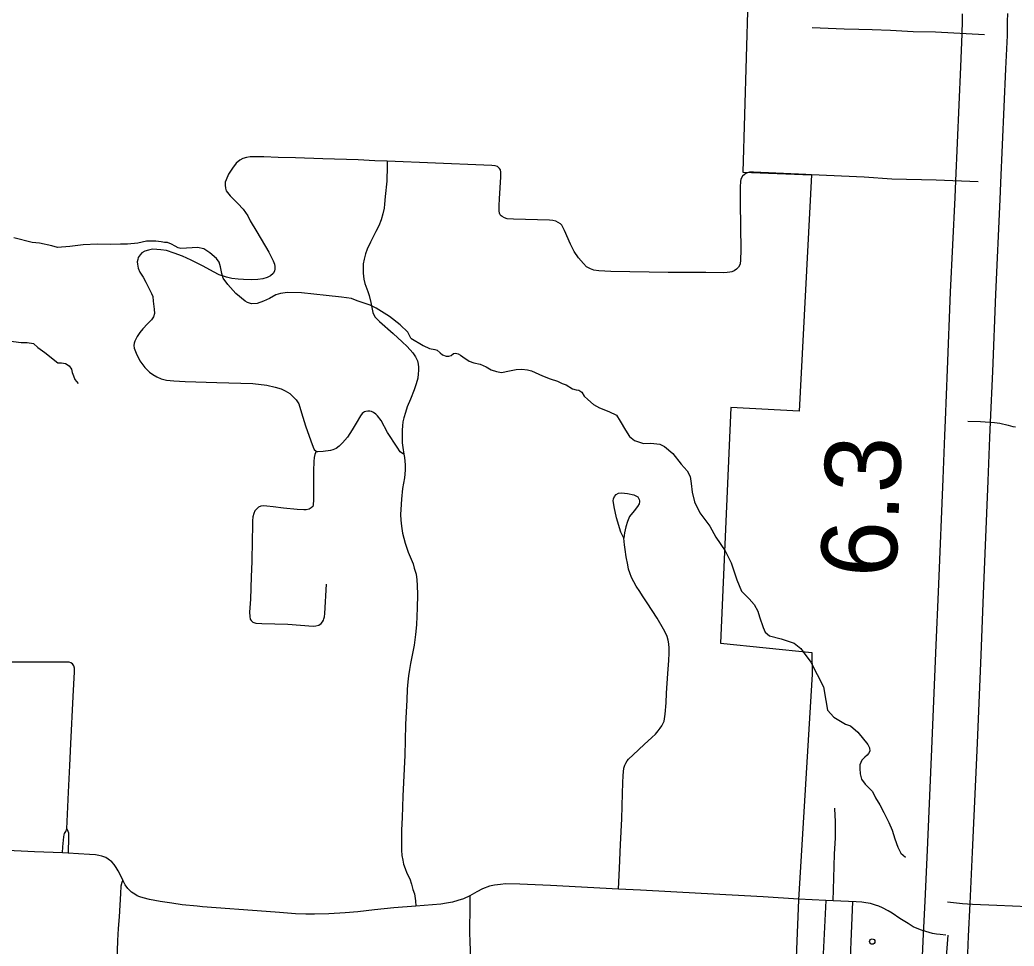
# Model space of a CAD drawing. Extents: x 653372 to 905732, y 627442 to 787275.
# Drawn here: x 684356 to 689902, y 750128 to 755293 of the extents above; entities that cross this region are included whole.
import ezdxf

# ---------------------------------------------------------------- set-up
doc = ezdxf.new("R2010")
doc.units = 0
for name, color, linetype in [('15', 7, 'Continuous'), ('33', 7, 'Continuous'), ('34', 7, 'Continuous'), ('35', 7, 'Continuous'), ('48', 7, 'Continuous'), ('57', 7, 'Continuous'), ('6', 7, 'Continuous')]:
    doc.layers.add(name, color=color, linetype=linetype)

msp = doc.modelspace()

# ---------------------------------------------------------------- linework, layer by layer
at = {"layer": '15'}
for points in [[(689519.6, 753060.5), (689531.2, 753342.1), (689548.2, 753773.6), (689572.7, 754302.1), (689576.4, 754395.3), (689605, 755029.9), (689612.9, 755214.1), (689614.3, 755287), (689614.8, 755325.5)], [(689864.8, 755329), (689864.3, 755283.1), (689862.8, 755206.4), (689854.8, 755018.9), (689826.2, 754384.7), (689822.5, 754291.3), (689798, 753762.9), (689781, 753332), (689769.4, 753050.2)], [(689386.5, 749952.9), (689396.2, 750194.9), (689405.6, 750377.4), (689419, 750662.4), (689445.9, 751269.7), (689466.3, 751762.7), (689482.6, 752146.3), (689505.8, 752732.5), (689516.2, 752975), (689519.6, 753060.5)], [(689769.4, 753050.2), (689766, 752964.7), (689755.6, 752722.2), (689732.4, 752136.1), (689716.1, 751752.2), (689695.7, 751258.9), (689668.7, 750651), (689655.3, 750365.1), (689645.9, 750183.4), (689636.3, 749941.9)]]:
    msp.add_lwpolyline(points, dxfattribs=at)
at = {"layer": '33'}
for points in [[(688775.2, 755250), (688953.6, 755241.8), (689035.3, 755240.7), (689111.4, 755238.5), (689212.8, 755236.1), (689338.5, 755227.4), (689464.3, 755225.7), (689737.9, 755210.3)], [(686405.1, 754504.9), (686335.6, 754506.8), (686242.8, 754512.2), (686045.9, 754517.6), (685893.7, 754522.7), (685797.7, 754525.6), (685717.1, 754529), (685640.4, 754529.2), (685620.3, 754525.6), (685599.7, 754520.5), (685583.1, 754511), (685562.7, 754493.2), (685541.4, 754466), (685519.9, 754433), (685506.9, 754401.4), (685502.2, 754386.8), (685501.2, 754370.5), (685503.4, 754354.7), (685507.1, 754339.4), (685528.3, 754311.8), (685540.6, 754299.8), (685572.3, 754268.9), (685601.7, 754236.5), (685626.9, 754200.6), (685640.7, 754171.2), (685677.8, 754111.3)], [(686405.1, 754504.9), (686405.9, 754476.6), (686402.3, 754392.7), (686393.9, 754308.4), (686390.5, 754265.7), (686387.7, 754243.3), (686381.3, 754210.3), (686372.3, 754177.4), (686358.5, 754143.5), (686342, 754112.3), (686311.9, 754052.7), (686293.6, 754013.2), (686284.2, 753987.7), (686276.4, 753959.1), (686271.9, 753932.5), (686270.5, 753905.2), (686270.3, 753881.1), (686272.5, 753863.9), (686275.2, 753846.7), (686280.9, 753821.9), (686297.7, 753777.4), (686304.6, 753755.8), (686313.6, 753717), (686325.3, 753661.5), (686336.8, 753636), (686361.7, 753610.1), (686438.3, 753543.1), (686489.4, 753496.6), (686516.9, 753471), (686548.5, 753435.2), (686563.3, 753412.9), (686573.4, 753390.6), (686577.1, 753372.8), (686579.8, 753356.2), (686579.8, 753337.4), (686578.7, 753318.7), (686575.9, 753295.3), (686566.9, 753262.4), (686555.2, 753230.1), (686535.4, 753178.2), (686516.5, 753134.2), (686507, 753102.9), (686497.5, 753072.7), (686492.6, 753051.4), (686490.3, 753029), (686488.5, 753005), (686488, 752971.8), (686489, 752933.8), (686492.5, 752907.5), (686497.9, 752871.5)], [(689701.3, 754390), (689466.7, 754397.9), (689219.8, 754405.3), (689065.8, 754415.4), (688771.7, 754428.8), (688741.3, 754430.2), (688449.2, 754442.9), (688427.1, 754442.9), (688409, 754438.6), (688397.7, 754430.7), (688387.1, 754420.6), (688377.6, 754403.7), (688376.5, 754391.3), (688374.3, 754361.6), (688373.8, 754346.4), (688373.7, 754273.2), (688377.5, 754007.7), (688376.5, 753953.9), (688373.8, 753930.5), (688364.9, 753912.8), (688353.6, 753902.1), (688340.9, 753892.8), (688326.9, 753887.7), (688317.2, 753885.9), (688302.6, 753883.6), (688281.2, 753882.8), (688183.2, 753883), (687972.9, 753883.8), (687652.4, 753889.3), (687584.9, 753894.1), (687558.8, 753897.6), (687539.7, 753904.4), (687517.9, 753916.1), (687500.5, 753934.6), (687473.2, 753965.8), (687448, 754001.8), (687427.8, 754041.8), (687394.9, 754118.7), (687379.9, 754147.5), (687371.2, 754156), (687359, 754163.3), (687346.1, 754170.6), (687330, 754174.5), (687310.1, 754176.5), (687109.3, 754181.9), (687074.8, 754183.6), (687059.1, 754188.2), (687046.2, 754196.2), (687040.8, 754200.5), (687036.1, 754204.8), (687030.9, 754213.9), (687029.2, 754228.5), (687029.4, 754257.5), (687031.2, 754294.7), (687039.1, 754417.8), (687039.2, 754444.1), (687036.8, 754457.2), (687031.5, 754463.6), (687020.1, 754474.3), (687007.7, 754478.1), (686989.2, 754480.8), (686944.3, 754482.1), (686405.1, 754504.9)], [(685100.4, 753723.5), (685105.4, 753678.6), (685106.3, 753655), (685101.5, 753637.3), (685090, 753619.2), (685067.8, 753597.3), (685042.3, 753569.7), (685025.4, 753549.2), (685010.5, 753527.4), (684998.2, 753501), (684994.2, 753489.6), (684992.7, 753477.5), (684994.4, 753462.8), (685004.1, 753434.6), (685025.3, 753390.9), (685052.6, 753354.4), (685079.6, 753327.8), (685098.1, 753314.6), (685120.8, 753301.4), (685143.6, 753291.2), (685174.9, 753284), (685214.2, 753280.2), (685278.7, 753276.1), (685454.8, 753270.1), (685655, 753264.3), (685734, 753255.6), (685780.9, 753244.2), (685814.3, 753234.3), (685836, 753224.2), (685861.8, 753208.7), (685879.2, 753192.9), (685896.5, 753174.6), (685911.6, 753152.3), (685927.9, 753101.4), (685948.9, 753029.3), (685978.9, 752945.9), (685991.7, 752909.4), (685998.6, 752896.7), (686009.4, 752886.8), (686016.6, 752884)], [(686497.9, 752871.5), (686490.2, 752874), (686478.2, 752884), (686460.3, 752910.7), (686407, 752991.6), (686371.6, 753058.4), (686351, 753085.3), (686342.2, 753094.6), (686328, 753103.1), (686318, 753108.7), (686309, 753111.2), (686297.2, 753111.5), (686286.5, 753109.7), (686279.4, 753106.7), (686273.5, 753103.7), (686265.8, 753096.9), (686256.3, 753084.9), (686231.5, 753042.8), (686209.8, 753007.1), (686183.5, 752966.2), (686155.7, 752933.8), (686136.5, 752915.1), (686120.1, 752903.3), (686101.6, 752895.8), (686089.8, 752891.9), (686048.9, 752885.6), (686016.6, 752884)], [(689644.5, 753055.3), (689714.7, 753053.7), (689793.6, 753048), (689823.6, 753043.2), (689868.8, 753032.5), (689894.9, 753025.4), (689910.1, 753022.8)], [(686497.9, 752871.5), (686502.6, 752851.4), (686505.4, 752811.1), (686505.8, 752780.9), (686502.6, 752738.8), (686490, 752678.8), (686484.2, 752619.3), (686481.2, 752563), (686479, 752534.2), (686482.1, 752502.6), (686484.4, 752469), (686489.9, 752429.6), (686505.7, 752374.8), (686522.3, 752324.6), (686549.9, 752260.1), (686556.5, 752235.7), (686566.9, 752202.3), (686571.3, 752170.6), (686573, 752137.7), (686573.5, 752087.4), (686572.6, 752011.7), (686571.2, 751966.8), (686567.8, 751919.9), (686562.2, 751865.5), (686555, 751805.3), (686544, 751750.7), (686535.2, 751704), (686530.1, 751669.9), (686523.7, 751633.9), (686520.7, 751601.1), (686516.1, 751560.8), (686514.9, 751498.4), (686511, 751433.5), (686508.2, 751363.2), (686505.5, 751274), (686503.8, 751192.9), (686492.8, 750963.2), (686487.9, 750845.3), (686485.8, 750774.9), (686484.7, 750714.6), (686485.8, 750662.9), (686487.6, 750632.3), (686491.5, 750607.3), (686496.9, 750584.4), (686505.5, 750559.5), (686515.5, 750533.5), (686531.3, 750502.2), (686540.5, 750473.1), (686549, 750444), (686556.9, 750418.2), (686563.1, 750380), (686565.6, 750351.1)], [(687726, 752403), (687708.3, 752436.7), (687685, 752516.3), (687671.9, 752576.6), (687666.7, 752600.5), (687665, 752610.8), (687667.3, 752621), (687673.6, 752634.2), (687683.4, 752645.3), (687695, 752652.5), (687711.3, 752655.2), (687746.3, 752652.1), (687781.2, 752644), (687792.5, 752639.3), (687802.9, 752633.1), (687807.8, 752625.4), (687811.2, 752618.6), (687812.6, 752611.5), (687812.7, 752604.8), (687810, 752593.4), (687802.1, 752579), (687782, 752555.2), (687756.6, 752522.4), (687745.2, 752495.9), (687736, 752465.4), (687729.8, 752432.1), (687726, 752403)], [(687694.8, 750445.3), (687701.1, 750562.7), (687707.4, 750693.5), (687713.7, 750837), (687717.9, 750978.1), (687719.3, 751037.9), (687721.3, 751079.6), (687723.1, 751098.9), (687726.1, 751119.9), (687730.9, 751136.3), (687735.6, 751146.8), (687743.9, 751161.1), (687750.5, 751169.6), (687778, 751194.4), (687839.3, 751251.4), (687880.7, 751290), (687901.4, 751309.9), (687916.9, 751327.6), (687928.4, 751342.2), (687937.3, 751356.7), (687944.9, 751370.3), (687949.9, 751382.3), (687952.7, 751395.7), (687955, 751420.4), (687960.9, 751484.6), (687964.1, 751538.1), (687971.3, 751646.9), (687977, 751719.8), (687978.3, 751760.4), (687978.4, 751789.9), (687977.1, 751813.3), (687973.4, 751833.5), (687967.3, 751854.3), (687958.4, 751875.1), (687946.4, 751895.2), (687910.8, 751955.8), (687856.2, 752041.9), (687829.9, 752080.6), (687814.8, 752104.3), (687794.1, 752134.5), (687780.2, 752159.8), (687768.7, 752183.4), (687758.4, 752209), (687752, 752230.1), (687746.8, 752254.3), (687739, 752298.7), (687732, 752339.7), (687729.2, 752365.8), (687726, 752403)], [(684618.7, 750781.5), (684627.2, 750986.4), (684635.2, 751135.5), (684640.5, 751255.2), (684652.5, 751519), (684660.2, 751657.4), (684660.8, 751677.8), (684656.5, 751689.7), (684649.2, 751701), (684641.2, 751707.7), (684631.4, 751711.5), (684621.5, 751711.8), (684311.4, 751710.6), (683991.3, 751710.8), (683355.8, 751710)], [(684594.2, 750647.4), (684596.1, 750681.2), (684601, 750737.8), (684603, 750747.7), (684605.9, 750755), (684611.8, 750766.8), (684618.7, 750781.5), (684624.1, 750767.6), (684627.1, 750758.4), (684628.2, 750749), (684628.2, 750737.6), (684625.1, 750645.6)], [(685262.3, 750358.6), (685204.3, 750366.1), (685137.9, 750377.1), (685078.6, 750388), (685044.1, 750396.7), (685024.7, 750403), (685011.1, 750408.6), (684996.5, 750417.6), (684979.7, 750429.1), (684958.9, 750448.8), (684943.7, 750468.4), (684929.7, 750495), (684917.7, 750522.6), (684904.6, 750547.3), (684893.7, 750565.7), (684882.3, 750583.2), (684869.1, 750597.9), (684849.5, 750612.3), (684835.9, 750620.8), (684812.4, 750629.6), (684796.3, 750633.5), (684778.7, 750636.4), (684744.9, 750638.4), (684683.5, 750642.6), (684625.1, 750645.6), (684594.2, 750647.4), (684438, 750653.3), (684250.7, 750661.7)], [(689521, 750189.2), (689489.5, 750192.4), (689468.8, 750194.4), (689448, 750198.3), (689410.8, 750209.5), (689380.1, 750218.5), (689339.7, 750235.9), (689310.6, 750252.9), (689265.8, 750281.8), (689221.7, 750311.3), (689200.6, 750324.7), (689168.8, 750340.5), (689148.3, 750349.8), (689128.3, 750356.5), (689101, 750364.7), (689075.6, 750369.5), (689052.2, 750373.5), (689021.4, 750375.1), (688892.9, 750380.5), (688851.9, 750381.6), (688699.6, 750388.8), (688503.4, 750402.1), (688157.1, 750421.3), (687819, 750438.8), (687694.8, 750445.3), (687316.4, 750466), (687145.7, 750473.1), (687065.8, 750474.2), (687036.8, 750471), (687004.4, 750467.3), (686976.1, 750462.1), (686936.6, 750447.1), (686905.2, 750429.9), (686866.8, 750407.6), (686830.2, 750391.9), (686799.3, 750381.8), (686769.1, 750372.9), (686736.4, 750367.1), (686704.7, 750362), (686657.5, 750357.4), (686565.6, 750351.1), (686441.6, 750341), (686335.1, 750329.5), (686242, 750318.8), (686170.3, 750312.9), (686080.1, 750308.2), (685998.8, 750306.6), (685950.4, 750306.1), (685893.4, 750308.4), (685804.9, 750314.5), (685729.8, 750320.8), (685375, 750346.2), (685345.5, 750349.8), (685262.3, 750358.6)], [(686866.8, 750407.6), (686865.9, 750378), (686865.3, 750318.3), (686863.5, 750241.3), (686865.1, 750198.3), (686865.7, 750157.7), (686870.4, 750044.5)], [(688851.9, 750381.6), (688827.3, 749899.1), (688811.5, 749450.7), (688797.9, 749228.5), (688799.3, 749199.4), (688808, 749180.6), (688822.6, 749165.1), (688843.3, 749157.5), (688860.6, 749155.8), (689243.8, 749139.1)], [(689530.6, 750373.9), (689564.9, 750370.1), (689615.2, 750365.8), (689669.7, 750362.1), (689805.2, 750355.2), (690068, 750345.2)]]:
    msp.add_lwpolyline(points, dxfattribs=at)
at = {"layer": '34'}
for points in [[(685677.8, 754111.3), (685744.8, 753996.4), (685769.1, 753948.9), (685776.9, 753930.3), (685778.1, 753918.2), (685778.2, 753904), (685775.7, 753890.9), (685769.1, 753879), (685753.4, 753864.8), (685735.8, 753855.9), (685712, 753849.2), (685683.5, 753844.3), (685648.2, 753842.2), (685604.2, 753845.1), (685573.3, 753846.6), (685538.2, 753850.8), (685509, 753858.5), (685466.9, 753871.3), (685435.4, 753888.5), (685378.9, 753919.1), (685311.6, 753952.7), (685264, 753974.6), (685216.7, 753992.3), (685173.5, 754005.7), (685142.7, 754010.8), (685120.2, 754013.1), (685095.5, 754013.8), (685073.3, 754009.2), (685052.7, 754003.5), (685035.5, 753993), (685026.3, 753982.8), (685016.4, 753967.8), (685013.4, 753956.9), (685010.4, 753943.9), (685012.6, 753929.6), (685016.7, 753908.5), (685025, 753886.7), (685043.6, 753858.3), (685058.5, 753829.5), (685075.3, 753796.7), (685089.6, 753766.3), (685097, 753749.8), (685100.4, 753723.5)], [(686009.4, 752886.8), (686001.5, 752868.2), (685997.8, 752852.6), (685995.1, 752830.1), (685993.5, 752778.1), (685993.4, 752616.8), (685992, 752588.5), (685989.7, 752579.7), (685981.7, 752570.7), (685970.8, 752564.5), (685953.9, 752560.8), (685940.2, 752560.1), (685903.5, 752561.7), (685826.5, 752569.3), (685769.2, 752576.6), (685733.6, 752580.2), (685715.7, 752582.1), (685700.5, 752580.5), (685687.7, 752575.1), (685675.3, 752564.9), (685667.7, 752555.2), (685660.9, 752540.1), (685656.2, 752521.4), (685654.4, 752499.4), (685654, 752468.7), (685652.2, 752390.5), (685649.7, 752271.8), (685645.6, 752187.7), (685641.8, 752062.3), (685636.5, 751989.4), (685638.4, 751964.7), (685640.1, 751951), (685646.1, 751942.9), (685656.4, 751934.7), (685662.1, 751931.4), (685673, 751928.4), (685705, 751927.5), (685850.3, 751922.1), (685992.9, 751912), (686007.1, 751913.1), (686024, 751917.9), (686036.4, 751927), (686043.5, 751935.2), (686049, 751944.5), (686052.4, 751951.7), (686054.8, 751964.2), (686057, 751983.1), (686066.4, 752146.2)], [(688892.9, 750380.5), (688897.2, 750506.1), (688900.1, 750640), (688905.7, 750730.7), (688905.8, 750773), (688905.6, 750825.7), (688904.2, 750854.8), (688901.4, 750897.7)], [(684929.7, 750495), (684924.4, 750481.5), (684919.9, 750461.9), (684916.9, 750421.8), (684909.1, 750291.2), (684904, 750225.7), (684901.6, 750158.2), (684897.7, 750042.8)]]:
    msp.add_lwpolyline(points, dxfattribs=at)
at = {"layer": '35'}
for points in [[(686536.8, 753518.3), (686521, 753551.4), (686478.3, 753592.6), (686417.2, 753638.4), (686342.8, 753684.5), (686310, 753701.5), (686237.6, 753726.3), (686206.4, 753738.5), (686150.7, 753745.5), (686065.3, 753756.1), (685926.7, 753770.2), (685849.2, 753772.5), (685809.7, 753766.4), (685783.6, 753758.5), (685747.7, 753739.6), (685715.3, 753723.3), (685679.7, 753710.4), (685647.7, 753709.4), (685626.7, 753716.7), (685612.7, 753723.7), (685560.8, 753766.6), (685515.7, 753817.1), (685490.8, 753851.8), (685483.6, 753878), (685476.1, 753915.4), (685468.2, 753941.6), (685452.2, 753962.1), (685415.3, 753994.3), (685382, 754015.3), (685346.3, 754023), (685316.4, 754021.9), (685285.7, 754019.5), (685254.4, 754018.5), (685239.9, 754021.6), (685222.9, 754030.7), (685201.3, 754042), (685178.9, 754051.3), (685162.5, 754051.7), (685143.6, 754055.2), (685114.9, 754058.5), (685063.2, 754058.8), (685013.6, 754048.3), (684956.2, 754041.4), (684917, 754041.2), (684864.4, 754040.1), (684788.7, 754041.7), (684709.4, 754037.5), (684634.7, 754028.4), (684565.7, 754024.1), (684533.7, 754032.7), (684465.2, 754047.5), (684425.4, 754050.7), (684322.2, 754077.7)], [(683875.5, 753777.5), (683928.3, 753714.2), (683992, 753674.7), (684058.7, 753654.9), (684087.2, 753637.3), (684124.4, 753616.3), (684162.4, 753592), (684197.3, 753560), (684225.2, 753524.3), (684277.9, 753504.7), (684363.3, 753494.1), (684397.1, 753493.1), (684432.8, 753488.1), (684456.1, 753465.4), (684495.1, 753438.3), (684567.1, 753380.4), (684588.7, 753380), (684609.8, 753376.9), (684631.2, 753364), (684643.3, 753345.2), (684647.7, 753326.1), (684655.1, 753306.9), (684663.5, 753287.8), (684681.7, 753264.3)], [(686536.8, 753518.3), (686606.7, 753477.6), (686641.3, 753459.3), (686670.2, 753454.9), (686684.6, 753450.4), (686700.7, 753436.8), (686714.2, 753424.6), (686734.7, 753417.8), (686749.1, 753416.6), (686761.7, 753421.8), (686775.2, 753433.1), (686787, 753434.9), (686800.6, 753430.3), (686813.5, 753423), (686827.7, 753412.9), (686862.7, 753389.1), (686888.6, 753379.3), (686923, 753372.8), (686957, 753357.9), (686985.5, 753340.5), (687014.3, 753332), (687043.1, 753325.6), (687086.8, 753334.7), (687124.3, 753342.5), (687156.2, 753344.3), (687188.5, 753341.3), (687210.4, 753335.1), (687272, 753307), (687314.3, 753291.2), (687355.9, 753278), (687381.6, 753264.8), (687403.6, 753257.5), (687438.2, 753235.6), (687458.7, 753229.2), (687473.4, 753228), (687491.4, 753216.3), (687503.3, 753193.7), (687524.2, 753176.5), (687556.5, 753147.9), (687589.1, 753128.5), (687641.6, 753108.3), (687683.7, 753087.7)], [(687683.7, 753087.7), (687704.8, 753055.8), (687734.8, 753003.9), (687756.3, 752970.2), (687785.6, 752946.8), (687834.6, 752930.3), (687876.7, 752932), (687926, 752926.1), (687952.6, 752913.3), (687998, 752874.4), (688045.7, 752814.4), (688079.2, 752778.8), (688094.7, 752746.9), (688101, 752707.6), (688107.1, 752659.4), (688119, 752605), (688148.6, 752544.1), (688204.9, 752468.8), (688239.1, 752407.8), (688290.9, 752332.6), (688323.4, 752265.6), (688355, 752170.8), (688381.6, 752107), (688425.3, 752063.7), (688452.9, 752032.8), (688472.8, 751994.7), (688482.3, 751962.9), (688501.6, 751903.7), (688512.8, 751877.9), (688537.6, 751857.5), (688602.4, 751840.2), (688676.2, 751817.6), (688713.1, 751787.9), (688726.2, 751769.4), (688768, 751711.1), (688803.5, 751642.5), (688838.9, 751573.9), (688852.3, 751498.1), (688860.8, 751443.8), (688896.4, 751405), (688961.7, 751365.7), (688989.9, 751355.9), (689030.9, 751320.1), (689086.7, 751252.4), (689095.8, 751233.6), (689096.8, 751214.3), (689090.9, 751202.2), (689082.3, 751191.7), (689069.2, 751180.9), (689052.9, 751164), (689041.5, 751139.3), (689041.8, 751118.4), (689043.5, 751088.8), (689051.4, 751057.6), (689070.8, 751030.8), (689113.3, 750989.5), (689129.7, 750954.1), (689152.8, 750915.3), (689175.5, 750873.3), (689204.4, 750817.3), (689221.6, 750774.4), (689236.9, 750726.4), (689253.6, 750678.6), (689271, 750646.5), (689295.8, 750624.3)]]:
    msp.add_lwpolyline(points, dxfattribs=at)
at = {"layer": '57'}
msp.add_circle((689111.2, 750153), 15, dxfattribs=at)
at = {"layer": '6'}
for points in [[(688416.5, 755402.8), (688389.5, 754444.1), (688771.7, 754428.8), (688702.5, 753109.9), (688321.9, 753131.2), (688264.2, 751816.3), (688773.3, 751765.3), (688776.2, 751644.4), (688700.4, 750386.2), (688649.8, 749137.7), (688482, 749146.2), (688421.4, 747822.2)], [(689532.1, 750188), (689526, 750091.5), (689519.7, 749933), (689516.4, 749861.1), (688981.9, 749882.3), (689003, 750375.9)]]:
    msp.add_lwpolyline(points, dxfattribs=at)

# ---------------------------------------------------------------- texts
at = {"layer": '48'}
msp.add_text('6.3', height=422.4, rotation=87.641, dxfattribs=at).set_placement((689243.5, 752177.7))

doc.saveas('drawing.dxf')
